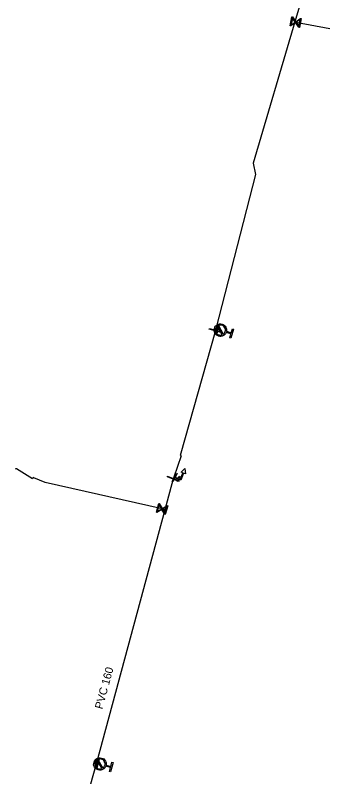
# Model space of a CAD drawing. Extents: x -643544 to -637295, y -1119190 to -1111715.
# Drawn here: x -642435.6 to -642384.5, y -1114876.1 to -1114752.4 of the extents above; entities that cross this region are included whole.
import ezdxf

# ---------------------------------------------------------------- set-up
doc = ezdxf.new("R2010")
doc.units = 0
for name, color, linetype in [('Default', 7, 'Continuous'), ('VP Hydrant', 7, 'Continuous'), ('VP Přípojka', 7, 'Continuous'), ('VP Řad', 7, 'Continuous'), ('VP Řad - popis', 7, 'Continuous'), ('VP Šoupě', 7, 'Continuous')]:
    doc.layers.add(name, color=color, linetype=linetype)

msp = doc.modelspace()

# ---------------------------------------------------------------- linework, layer by layer
at = {"layer": 'Default'}
for points in [[(-642401.32, -1114803.94), (-642401.45, -1114804.28), (-642401.77, -1114804.45), (-642402.14, -1114804.65), (-642402.53, -1114804.53), (-642402.93, -1114804.41), (-642403.13, -1114804.05), (-642403.33, -1114803.68), (-642403.21, -1114803.29), (-642403.09, -1114802.89), (-642402.73, -1114802.69), (-642402.37, -1114802.49), (-642401.97, -1114802.61), (-642401.57, -1114802.73), (-642401.37, -1114803.09), (-642401.19, -1114803.41), (-642401.27, -1114803.76)], [(-642401.78, -1114804.24), (-642401.55, -1114804.08), (-642401.47, -1114803.8), (-642401.37, -1114803.47), (-642401.53, -1114803.18), (-642401.69, -1114802.88), (-642402.02, -1114802.79), (-642402.3, -1114802.71), (-642402.56, -1114802.82)], [(-642402.72, -1114802.9), (-642402.95, -1114803.06), (-642403.03, -1114803.34), (-642403.12, -1114803.66), (-642402.96, -1114803.96), (-642402.8, -1114804.25), (-642402.48, -1114804.35), (-642402.2, -1114804.43), (-642401.94, -1114804.32)], [(-642420.87, -1114874.39), (-642421, -1114874.73), (-642421.31, -1114874.91), (-642421.67, -1114875.11), (-642422.07, -1114875), (-642422.47, -1114874.9), (-642422.68, -1114874.54), (-642422.88, -1114874.18), (-642422.77, -1114873.77), (-642422.66, -1114873.38), (-642422.31, -1114873.17), (-642421.95, -1114872.97), (-642421.55, -1114873.08), (-642421.15, -1114873.18), (-642420.94, -1114873.54), (-642420.76, -1114873.86), (-642420.82, -1114874.21)], [(-642421.33, -1114874.7), (-642421.1, -1114874.54), (-642421.02, -1114874.25), (-642420.93, -1114873.93), (-642421.1, -1114873.64), (-642421.27, -1114873.34), (-642421.59, -1114873.26), (-642421.88, -1114873.18), (-642422.13, -1114873.29)], [(-642422.29, -1114873.38), (-642422.51, -1114873.55), (-642422.59, -1114873.82), (-642422.68, -1114874.15), (-642422.51, -1114874.44), (-642422.35, -1114874.73), (-642422.02, -1114874.82), (-642421.74, -1114874.9), (-642421.49, -1114874.79)]]:
    msp.add_open_spline(points, degree=3, dxfattribs=at)
at = {"layer": 'VP Hydrant'}
for points in [[(-642401.94, -1114804.32), (-642402.72, -1114802.9)], [(-642402.56, -1114802.82), (-642401.78, -1114804.24)], [(-642401.27, -1114803.76), (-642400.48, -1114804), (-642400.29, -1114803.33), (-642400.11, -1114803.39), (-642400.55, -1114804.88), (-642400.73, -1114804.83), (-642400.53, -1114804.17), (-642401.32, -1114803.94)], [(-642408.97, -1114827.69), (-642408.74, -1114827.78), (-642408.33, -1114826.73), (-642408.62, -1114826.62), (-642408, -1114826.06), (-642407.92, -1114826.89), (-642408.22, -1114826.78), (-642408.67, -1114827.94), (-642409.02, -1114827.8), (-642409.16, -1114828.15), (-642409.27, -1114828.1), (-642409.14, -1114827.76), (-642409.48, -1114827.62), (-642409.44, -1114827.5), (-642409.09, -1114827.64), (-642408.96, -1114827.29), (-642408.84, -1114827.34), (-642408.97, -1114827.69)], [(-642421.49, -1114874.79), (-642422.29, -1114873.38)], [(-642422.13, -1114873.29), (-642421.33, -1114874.7)], [(-642420.82, -1114874.21), (-642420.03, -1114874.43), (-642419.85, -1114873.77), (-642419.67, -1114873.81), (-642420.09, -1114875.32), (-642420.26, -1114875.27), (-642420.08, -1114874.61), (-642420.87, -1114874.39)]]:
    msp.add_lwpolyline(points, dxfattribs=at)
at = {"layer": 'VP Přípojka'}
for points in [[(-642390.16, -1114753.51), (-642390.01, -1114753.54), (-642384.47, -1114754.56)], [(-642402.25, -1114803.57), (-642402.69, -1114803.44), (-642403, -1114803.37)], [(-642435.49, -1114826.09), (-642435.57, -1114826.14)], [(-642411.27, -1114832.77), (-642411.72, -1114832.62), (-642430.7, -1114828.34), (-642432.56, -1114827.57), (-642432.68, -1114827.49), (-642432.78, -1114827.73), (-642435.34, -1114826.1), (-642435.49, -1114826.09)], [(-642409.47, -1114827.59), (-642409.66, -1114827.49), (-642409.78, -1114827.43)], [(-642421.81, -1114874.04), (-642422.17, -1114873.97), (-642422.39, -1114873.88)]]:
    msp.add_lwpolyline(points, dxfattribs=at)
at = {"layer": 'VP Řad'}
msp.add_lwpolyline([(-642386.93, -1114742.69), (-642390.16, -1114753.51), (-642396.9, -1114776.43), (-642396.53, -1114778.28), (-642403, -1114803.37), (-642403.06, -1114803.62), (-642408.76, -1114823.91), (-642408.6, -1114824.01), (-642409.78, -1114827.43), (-642409.9, -1114827.73), (-642411.27, -1114832.77), (-642422.39, -1114873.88), (-642424.45, -1114881.16), (-642429.6, -1114901.07), (-642431.22, -1114907.61), (-642432.79, -1114915.21), (-642432.85, -1114915.55)], dxfattribs=at)
at = {"layer": 'VP Šoupě'}
for points in [[(-642389.14, -1114752.94), (-642389.41, -1114754.41), (-642389.47, -1114754.4), (-642389.54, -1114754.29), (-642390.02, -1114753.6), (-642390.82, -1114754.15), (-642390.88, -1114754.14), (-642390.61, -1114752.67), (-642390.55, -1114752.68), (-642390, -1114753.48), (-642389.31, -1114753), (-642389.2, -1114752.93), (-642389.14, -1114752.94)], [(-642390.76, -1114754.01), (-642390.07, -1114753.53), (-642390.55, -1114752.84), (-642390.76, -1114754.01)], [(-642389.26, -1114753.08), (-642389.95, -1114753.55), (-642389.47, -1114754.24), (-642389.26, -1114753.08)], [(-642402.47, -1114802.72), (-642402.81, -1114804.19), (-642402.9, -1114804.16), (-642402.56, -1114802.7), (-642402.47, -1114802.72)], [(-642404.01, -1114803.3), (-642402.08, -1114803.82), (-642402.11, -1114803.94), (-642404.04, -1114803.42), (-642404.01, -1114803.3)], [(-642410.81, -1114827.31), (-642408.95, -1114828.04), (-642408.99, -1114828.15), (-642410.85, -1114827.42), (-642410.81, -1114827.31)], [(-642409.26, -1114826.85), (-642409.97, -1114828.18), (-642410.05, -1114828.13), (-642409.35, -1114826.81), (-642409.26, -1114826.85)], [(-642410.8, -1114832.09), (-642411.19, -1114833.54), (-642411.25, -1114833.52), (-642411.31, -1114833.41), (-642411.74, -1114832.69), (-642412.57, -1114833.17), (-642412.64, -1114833.16), (-642412.25, -1114831.71), (-642412.19, -1114831.72), (-642411.7, -1114832.56), (-642410.98, -1114832.14), (-642410.87, -1114832.08), (-642410.8, -1114832.09)], [(-642412.51, -1114833.03), (-642411.78, -1114832.61), (-642412.2, -1114831.88), (-642412.51, -1114833.03)], [(-642410.93, -1114832.22), (-642411.66, -1114832.64), (-642411.24, -1114833.36), (-642410.93, -1114832.22)], [(-642421.92, -1114873.26), (-642422.33, -1114874.7), (-642422.42, -1114874.68), (-642422.01, -1114873.24), (-642421.92, -1114873.26)]]:
    msp.add_lwpolyline(points, dxfattribs=at)

# ---------------------------------------------------------------- texts
at = {"layer": 'VP Řad - popis'}
msp.add_text('PVC 160', height=1.3, rotation=74.7161, dxfattribs=at).set_placement((-642421.42, -1114865.23))

doc.saveas('drawing.dxf')
